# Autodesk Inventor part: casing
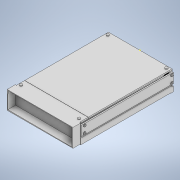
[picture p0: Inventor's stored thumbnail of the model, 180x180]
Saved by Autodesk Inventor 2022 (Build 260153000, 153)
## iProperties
Created: 2021-06
Part Number: casing
Material: Generic
Document SubType Name: Modeling
Designer: Dell
Density: 1 g/cm^3
Appearance: Default
Author: Dell
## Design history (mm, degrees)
sketch "Sketch1"
  geometry: L1 (-125, -25)-(125, -25); L2 (125, -25)-(125, 25); L3 (125, 25)-(-125, 25); L4 (-125, 25)-(-125, -25); L5 (-125, -25)-(125, 25); L6 (125, -25)-(-125, 25); 1 further point
  constraints: 12 end point, 2 midpoint, 2 parallel, 1 horizontal, 1 perpendicular
  dimensions: "d0" = 250 distance of L3.end L2.end; "d1" = 50 distance of L2.end L1.end
extrude "Extrusion1" new body sketch "Sketch1" distance "d2" = 10; taper "d3" = 0 deg
sketch "Sketch2"
  geometry: L1 (125, -25)-(125, 25) reference; L2 (-125, 25)-(-125, -25) reference; C1 r 5 at (-119.5, 17.804); C2 r 5 at (-119.5, -19.662); C3 r 5 at (119.5, -19.662); C4 r 5 at (119.5, 17.804); 1 further point
  constraints: 4 centre point
  dimensions: "d4" = 10 diameter of C1; "d5" = 10 diameter of C2; "d6" = 10 diameter of C3; "d7" = 10 diameter of C4; "d8" = 5.5 distance from line of L1 C3.centre; "d9" = 5.5 distance from line of L1 C4.centre; "d10" = 5.5 distance from line of L2 C1.centre; "d11" = 5.5 distance from line of L2 C2.centre
extrude "Extrusion2" join sketch "Sketch2" distance "d12" = 350; taper "d13" = 0 deg
sketch "Sketch3"
  geometry: C1 r 5 at (-119.5, 17.804) reference; C2 r 5.64 at (-119.5, 17.804); 1 further point
  constraints: 1 centre point, 1 coincident
extrude "Extrusion3" join sketch "Sketch3" distance "d14" = 20; taper "d15" = 0 deg
sketch "Sketch4"
  geometry: C1 r 5 at (119.5, 17.804) reference; C2 r 5.25 at (119.5, 17.804); C3 r 5.25 at (119.5, -20.116); C4 r 5.25 at (-119.54, -20.116); 1 further point
  constraints: 3 centre point, 1 coincident
  dimensions: "d16" = 10.5 diameter of C2; "d17" = 10.5 diameter of C3; "d18" = 10.5 diameter of C4
extrude "Extrusion4" join sketch "Sketch4" distance "d19" = 20; taper "d20" = 0 deg
sketch "Sketch5"
  geometry: C1 r 5 at (-99.537, 0); C2 r 5 at (-53.545, 0); C3 r 5 at (38.02, 0); C4 r 5 at (93.254, 0); 1 further point
  constraints: 4 centre point
  dimensions: "d21" = 10 diameter of C1; "d22" = 10 diameter of C2; "d23" = 10 diameter of C3; "d24" = 10 diameter of C4
extrude "Extrusion5" join sketch "Sketch5" distance "d25" = 200; taper "d26" = 0 deg
sketch "Sketch6"
  geometry: C1 r 5 at (100.739, 0); 1 further point
  constraints: 1 centre point
  dimensions: "d27" = 10 diameter of C1
extrude "Extrusion6" join sketch "Sketch6" distance "d28" = 200; taper "d29" = 0 deg
sketch "Sketch7"
  geometry: C1 r 5 at (-75.108, 0); C2 r 5 at (75.885, 0); 1 further point
  constraints: 2 centre point
  dimensions: "d30" = 10 diameter of C1; "d31" = 10 diameter of C2
extrude "Extrusion7" join sketch "Sketch7" distance "d32" = 100; taper "d33" = 0 deg
sketch "Sketch8"
  geometry: C1 r 5 at (75.885, 0) reference; C2 r 5.1 at (75.885, 0); C3 r 5 at (-75.108, 0) reference; C4 r 5.1 at (-75.108, 0); 1 further point
  constraints: 2 centre point, 2 coincident
  dimensions: "d34" = 10.2 diameter of C2; "d35" = 10.2 diameter of C4
extrude "Extrusion8" join sketch "Sketch8" distance "d36" = 150; taper "d37" = 0 deg
sketch "Sketch9"
  geometry: L1 (0, 7.931)-(-328.777, 7.931); L2 (-328.777, 7.931)-(-328.777, 45.876); L3 (-328.777, 45.876)-(0, 45.876); L4 (0, 45.876)-(0, 7.931); 1 further point
  constraints: 8 end point, 2 parallel, 1 horizontal, 1 perpendicular
extrude "Extrusion9" join sketch "Sketch9" distance "d38" = 5; taper "d39" = 0 deg
sketch "Sketch10"
  geometry: L1 (0, 45.876)-(0, 50) reference; L2 (0, 45.876)-(329.471, 45.876); L3 (329.471, 45.876)-(329.471, 4.229); L4 (329.471, 4.229)-(0, 4.229); L5 (0, 4.229)-(0, 45.876); 1 further point
  constraints: 8 end point, 2 parallel, 1 horizontal, 1 perpendicular
extrude "Extrusion10" join sketch "Sketch10" distance "d40" = 5; taper "d41" = 0 deg
sketch "Sketch11"
  geometry: L1 (249.75, 0)-(1.214, 0); L2 (1.214, 0)-(1.214, -327.338); L3 (1.214, -327.338)-(249.75, -327.338); L4 (249.75, -327.338)-(249.75, 0); 1 further point
  constraints: 8 end point, 2 parallel, 1 horizontal, 1 perpendicular
extrude "Extrusion11" join sketch "Sketch11" distance "d42" = 5; taper "d43" = 0 deg
sketch "Sketch12"
  geometry: L1 (30.654, 285.189)-(220.959, 285.189); L2 (220.959, 285.189)-(220.959, 280.351); L3 (220.959, 280.351)-(30.654, 280.351); L4 (30.654, 280.351)-(30.654, 285.189); 1 further point
  constraints: 8 end point, 2 parallel, 1 horizontal, 1 perpendicular
extrude "Extrusion12" join sketch "Sketch12" distance "d44" = 15; taper "d45" = 0 deg
sketch "Sketch13"
  geometry: 1 further point
sketch "Sketch14"
  geometry: L1 (249.5, -34.873)-(249.5, 3.072) reference; L2 (244.5, -34.873)-(244.5, 3.072) reference; L3 (249.5, -34.873)-(244.5, -34.873); L4 (244.5, -34.873)-(244.5, 3.072); L5 (244.5, 3.072)-(249.5, 3.072); L6 (249.5, 3.072)-(249.5, -34.873); L7 (244.25, 7.196)-(244.25, 12.196) reference; L8 (244.25, 7.196)-(-4.286, 7.196) reference; L9 (244.25, 12.196)-(-4.286, 12.196); L10 (-4.286, 12.196)-(-4.286, 7.196); L11 (-4.286, 7.196)-(244.25, 7.196); L12 (244.25, 7.196)-(244.25, 12.196); L13 (-5.5, -38.575)-(-10.5, -38.575) reference; L14 (-10.5, 3.072)-(-10.5, -38.575) reference; L15 (-5.5, -38.575)-(-10.5, -38.575); L16 (-10.5, -38.575)-(-10.5, 3.072); L17 (-10.5, 3.072)-(-5.5, 3.072); L18 (-5.5, 3.072)-(-5.5, -38.575); 3 further points
  constraints: 24 end point, 6 parallel, 3 horizontal, 3 perpendicular
extrude "Extrusion13" join sketch "Sketch14" distance "d46" = 32; taper "d47" = 0 deg
sketch "Sketch15"
  geometry: 1 further point
sketch "Sketch16"
  geometry: L1 (-8.634, -38.575)-(247.691, -38.575); L2 (247.691, -38.575)-(247.691, 12.196); L3 (247.691, 12.196)-(-8.634, 12.196); L4 (-8.634, 12.196)-(-8.634, -38.575); 1 further point
  constraints: 8 end point, 2 parallel, 1 horizontal, 1 perpendicular
extrude "Extrusion14" join sketch "Sketch16" distance "d48" = 2; taper "d49" = 0 deg
sketch "Sketch17"
  geometry: L1 (30.463, 210)-(20.463, 210) reference; L2 (30.463, 210)-(71.438, 137.486); L3 (71.438, 137.486)-(79.69, 142.149); L4 (79.69, 142.149)-(38.715, 214.663); L5 (38.715, 214.663)-(30.463, 210); L6 (182.656, 132.028)-(220.739, 210); L7 (220.739, 10)-(220.739, 210) reference; L8 (182.656, 132.028)-(176.036, 142.149); L9 (230.739, 210)-(220.739, 210) reference; L10 (220.739, 210)-(215.663, 218.984); L11 (215.663, 218.984)-(176.036, 142.149); 1 further point
  constraints: 16 end point, 3 perpendicular, 1 point on line
extrude "Extrusion15" join sketch "Sketch17" distance "d50" = 40; taper "d51" = 0 deg
sketch "Sketch18"
  geometry: L1 (-5, 360)-(-5, 0) reference; L2 (255, 360)-(255, 0) reference; L3 (-5, 9.92)-(255, 9.92); L4 (255, 9.92)-(255, 0); L5 (255, 0)-(-5, 0); L6 (-5, 0)-(-5, 9.92); 3 further points
  constraints: 8 end point, 2 parallel, 1 horizontal, 1 perpendicular, 1 point on line
extrude "Extrusion16" join sketch "Sketch18" distance "d52" = 20; taper "d53" = 0 deg
sketch "Sketch19"
  geometry: L1 (10, 4.229)-(360, 4.229) reference; L2 (30, 41.557)-(10, 41.557) reference; L3 (0, 7.931)-(10, 7.931) reference; C1 r 5 at (347.549, 40.186); C2 r 5 at (347.549, 9.229); C3 r 5 at (10, 41.557); C4 r 5 at (10, 7.931); 1 further point
  constraints: 4 centre point
  dimensions: "d54" = 10 diameter of C1; "d55" = 10 diameter of C2; "d56" = 5 distance from line of L1 C2.centre; "d57" = 10 diameter of C3; "d58" = 10 diameter of C4
extrude "Extrusion17" join sketch "Sketch19" distance "d59" = 2; taper "d60" = 0 deg
sketch "Sketch20"
  geometry: L1 (-0.609, 38.95)-(-0.609, 28.495); L2 (2.519, 37.944)-(-2.519, 37.944) reference; L3 (-0.609, 28.495)-(0, 28.495); L4 (0, 28.495)-(0, 38.21); L5 (0, 40.512)-(0, 29.233) reference; L6 (-0.609, 38.21)-(-0.609, 38.95); L7 (-0.609, 38.21)-(0, 38.21); 3 further points
  constraints: 10 end point, 2 point on line, 1 collinear, 1 horizontal, 1 perpendicular
extrude "Extrusion18" cut sketch "Sketch20" distance "d61" = 2; taper "d62" = 0 deg
sketch "Sketch21"
  geometry: L1 (0.419, 4.982)-(-0.435, 4.982); L2 (-0.435, 4.982)-(-0.435, -4.981); L3 (-0.435, -4.981)-(0.419, -4.981); L4 (0.419, -4.981)-(0.419, 4.982); L5 (337.549, 37.255)-(338.307, 37.255); L6 (338.307, 37.255)-(338.307, 36.579); L7 (338.307, 36.579)-(337.549, 36.579); L8 (337.549, 36.579)-(337.549, 37.255); L9 (338.307, 37.255)-(337.549, 37.255); L10 (337.549, 37.255)-(337.549, 27.255); L11 (337.549, 27.255)-(338.307, 27.255); L12 (338.307, 27.255)-(338.307, 37.255); L13 (337.549, -3.702)-(338.307, -3.702); L14 (338.307, -3.702)-(338.307, 6.24); L15 (338.307, 6.24)-(337.549, 6.24); L16 (337.549, 6.24)-(337.549, -3.702); A1 r 5 centre (0, 0) between (3.361, -3.702) and (-3.361, -3.702) reference; A2 r 5 centre (0, 0) between (-3.361, -3.702) and (3.361, -3.702) reference; A3 r 5 centre (337.549, 32.255) between (337.549, 37.255) and (337.549, 27.255) reference; A4 r 5 centre (337.549, 1.298) between (337.549, -3.702) and (338.307, 6.24) reference; 3 further points
  constraints: 32 end point, 8 parallel, 5 point on circle, 4 horizontal, 4 perpendicular, 2 point on line
extrude "Extrusion19" cut sketch "Sketch21" distance "d63" = 2; taper "d64" = 0 deg
sketch "Sketch22"
  geometry: C1 r 5 at (-347.549, 40.186); C2 r 5 at (-348.307, 14.171); C3 r 5 at (-6.62, 40.186); C4 r 5 at (-6.639, 12.912); A1 r 5 centre (-347.549, 40.186) between (-348.307, 45.129) and (-348.307, 35.244) reference; A2 r 5 centre (-347.549, 9.229) between (-348.307, 14.171) and (-348.307, 4.287) reference; 3 further points
  constraints: 4 centre point, 1 coincident
  dimensions: "d65" = 10 diameter of C1; "d66" = 10 diameter of C2; "d67" = 10 diameter of C3; "d68" = 10 diameter of C4
extrude "Extrusion20" join sketch "Sketch22" distance "d69" = 2; taper "d70" = 0 deg
sketch "Sketch23"
  geometry: L1 (-0.861, 3.238)-(0.719, 3.238); L2 (0.719, 3.238)-(0.719, -5.192); L3 (0.719, -5.192)-(-0.861, -5.192); L4 (-0.861, -5.192)-(-0.861, 3.238); L5 (-0.861, -22.345)-(0.719, -22.345); L6 (0.719, -22.345)-(0.719, -29.392); L7 (0.719, -29.392)-(-0.861, -29.392); L8 (-0.861, -29.392)-(-0.861, -22.345); L9 (-342.471, 3.238)-(-340.304, 3.238); L10 (-340.304, 3.238)-(-340.304, -5.192); L11 (-340.304, -5.192)-(-342.471, -5.192); L12 (-342.471, -5.192)-(-342.471, 3.238); L13 (-341.687, -21.015)-(-340.929, -21.015); L14 (-340.929, -21.015)-(-340.929, -30.957); L15 (-340.929, -30.957)-(-341.687, -30.957); L16 (-341.687, -30.957)-(-341.687, -21.015); A1 r 5 centre (-0.019, -27.274) between (0.416, -32.255) and (-0.455, -32.255) reference; A2 r 5 centre (-3.38, -32.255) between (-2.945, -37.236) and (-2.945, -27.274) reference; A3 r 5 centre (-340.929, -30.957) between (-341.687, -26.015) and (-341.687, -35.899) reference; 1 further point
  constraints: 32 end point, 8 parallel, 4 horizontal, 4 perpendicular, 4 point on line, 2 point on circle, 1 vertical alignment, 1 other
extrude "Extrusion21" cut sketch "Sketch23" distance "d71" = 2; taper "d72" = 0 deg
sketch "Sketch24"
  geometry: L1 (10.5, -30)-(10.5, -360) reference; L2 (7.386, -10)-(242.574, -10) reference; C1 r 5 at (237.545, -351.159); C2 r 5 at (10.5, -351.159); C3 r 5 at (10.5, -12.076); C4 r 5 at (237.545, -10); 1 further point
  constraints: 4 centre point, 2 point on line
  dimensions: "d73" = 10 diameter of C1; "d74" = 10 diameter of C2; "d75" = 10 diameter of C3; "d76" = 10 diameter of C4
extrude "Extrusion22" join sketch "Sketch24" distance "d77" = 3; taper "d78" = 0 deg
sketch "Sketch25"
  geometry: 1 further point
sketch "Sketch26"
  geometry: L1 (-9.161, 0)-(-13.51, 0) reference; L2 (-13.51, 0)-(-9.161, 0); L3 (-10.375, -350)-(-10.375, 0) reference; L4 (-9.161, 0)-(-10.375, -350); L5 (-15.375, -349.581)-(-15.375, -346.639) reference; L6 (-10.375, -350)-(-15.375, -346.639); L7 (-15.375, -11.693)-(-15.375, -7.451) reference; L8 (-15.375, -346.639)-(-13.51, 0); L9 (242.815, 0)-(244.625, 0) reference; L10 (244.625, 0)-(244.625, -352.925) reference; L11 (244.625, 0)-(244.625, -352.925); L12 (244.625, -352.925)-(239.375, -352.925); L13 (239.375, 0)-(239.375, -32) reference; L14 (239.375, -352.925)-(239.375, 0); L15 (239.375, 0)-(244.625, 0); 3 further points
  constraints: 16 end point, 2 collinear, 2 perpendicular, 1 horizontal
extrude "Extrusion23" join sketch "Sketch26" distance "d79" = 23; taper "d80" = 0 deg
sketch "Sketch27"
  geometry: L1 (-13.51, 0)-(-13.51, 2) reference; L2 (244.625, 0)-(239.375, 0) reference; L3 (-13.51, 2)-(244.625, 2); L4 (244.625, 2)-(244.625, 0); L5 (244.625, 0)-(-13.51, 0); L6 (-13.51, 0)-(-13.51, 2); 3 further points
  constraints: 8 end point, 2 parallel, 1 horizontal, 1 perpendicular
extrude "Extrusion24" join sketch "Sketch27" distance "d81" = 23; taper "d82" = 0 deg
sketch "Sketch28"
  geometry: L1 (-10.375, 0)-(-9.751, 0) reference; L2 (239.625, -360)-(239.625, -350) reference; L3 (-10.375, 0)-(239.625, 0); L4 (239.625, 0)-(239.625, -355); L5 (239.625, -355)-(-10.375, -355); L6 (-10.375, -355)-(-10.375, 0); 3 further points
  constraints: 8 end point, 2 parallel, 1 horizontal, 1 midpoint, 1 perpendicular
extrude "Extrusion25" join sketch "Sketch28" distance "d83" = 2; taper "d84" = 0 deg
sketch "Sketch29"
  geometry: L1 (239.625, 0)-(-10.375, 0) reference; L2 (239.625, -350.08)-(239.625, -355) reference; L3 (-10.375, 0)-(239.625, 0); L4 (239.625, 0)-(239.625, -355); L5 (239.625, -355)-(-10.375, -355); L6 (-10.375, -355)-(-10.375, 0); 3 further points
  constraints: 8 end point, 2 parallel, 1 horizontal, 1 perpendicular
extrude "Extrusion26" cut sketch "Sketch29" distance "d85" = 5; taper "d86" = 0 deg
sketch "Sketch30"
  geometry: 1 further point
sketch "Sketch31"
  geometry: 1 further point
sketch "Sketch32"
  geometry: C1 r 5.1 at (0, 0); C2 r 5.1 at (200.277, 0); A1 r 5 centre (200.277, 0) between (195.277, 0) and (205.277, 0) reference; 3 further points
  constraints: 2 centre point, 2 coincident, 1 horizontal alignment
  dimensions: "d87" = 10.2 diameter of C1; "d88" = 10.2 diameter of C2
extrude "Extrusion27" cut sketch "Sketch32" distance "d89" = 200; taper "d90" = 0 deg
sketch "Sketch33"
  geometry: 1 further point
sketch "Sketch34"
  geometry: 1 further point
sketch "Sketch35"
  geometry: C1 r 5.1 at (75.885, 0); C2 r 5.1 at (-75.108, 0) reference; C3 r 5.1 at (-75.108, 0); A1 r 5 centre (75.885, 0) between (71.318, -2.036) and (71.318, 2.036) reference; 1 further point
  constraints: 2 centre point, 2 coincident
  dimensions: "d91" = 10.2 diameter of C1; "d92" = 10.2 diameter of C3
extrude "Extrusion28" cut sketch "Sketch35" distance "d93" = 150; taper "d94" = 0 deg
sketch "Sketch36"
  geometry: L1 (190.818, -20.075)-(190.818, -15.534) reference; C1 r 10 at (190.818, -15.534); C2 r 10 at (59.499, -15.534); 1 further point
  constraints: 2 centre point
  dimensions: "d95" = 20 diameter of C1; "d97" = 20 diameter of C2
sketch "Sketch37"
  geometry: 1 further point
sketch "Sketch38"
  geometry: L1 (-8.634, 12.196)-(-8.634, 3.072) reference; L2 (-8.634, 12.196)-(248.986, 12.196); L3 (248.986, 12.196)-(248.986, -58.575); L4 (248.986, -58.575)-(-8.634, -58.575); L5 (-8.634, -58.575)-(-8.634, 12.196); L6 (-0.301, 9.828)-(244.25, 9.828); L7 (244.25, 7.196)-(-4.286, 7.196) reference; L8 (244.25, 9.828)-(244.25, -56.252); L9 (244.25, -56.252)-(-5.5, -54.724); L10 (-5.5, -54.724)-(-5.105, 9.828); L11 (-5.105, 9.828)-(-0.301, 9.828); C1 r 10 at (43.57, -17.804); 2 further points
  constraints: 18 end point, 3 parallel, 2 perpendicular, 1 centre point, 1 collinear, 1 horizontal, 1 point on line
  dimensions: "d96" = 20 diameter of C1
extrude "Extrusion29" join sketch "Sketch36" distance "d98" = 15; taper "d99" = 0 deg
sketch "Sketch39"
  geometry: 1 further point
sketch "Sketch40"
  geometry: L1 (38.587, 105.488)-(208.523, 105.488); L2 (38.587, 105.488)-(38.587, 97.395); L3 (38.587, 97.395)-(208.523, 97.395); L4 (208.523, 97.395)-(208.523, 105.488); 1 further point
  constraints: 8 end point, 2 perpendicular, 1 horizontal, 1 vertical
extrude "Extrusion30" join sketch "Sketch40" distance "d100" = 40; taper "d101" = 0 deg
sketch "Sketch41"
  geometry: L1 (22.478, -5)-(150.349, -5); L2 (150.349, -5)-(150.349, -35); L3 (150.349, -35)-(22.478, -35); L4 (22.478, -35)-(22.478, -5); L5 (25.478, -8)-(144.735, -8); L6 (0, 0)-(169.936, 0) reference; L7 (25.478, -32.733)-(25.478, -8); L8 (169.936, -40)-(0, -40) reference; L9 (25.478, -32.733)-(144.735, -31.501); L10 (144.735, -31.501)-(149.152, -31.455); L11 (149.152, -31.455)-(148.909, -7.957); L12 (148.909, -7.957)-(144.735, -8); 1 further point
  constraints: 20 end point, 3 perpendicular, 2 horizontal, 2 parallel, 1 point on line, 1 vertical
  dimensions: "d102" = 5 distance between parallel lines of L1 L6; "d103" = 3 distance between parallel lines of L5 L1; "d104" = 3 distance between parallel lines of L7 L4; "d105" = 5 distance between parallel lines of L8 L3
extrude "Extrusion31" join sketch "Sketch41" distance "d106" = 17; taper "d107" = 0 deg
extrude "Extrusion32" join sketch "Sketch38" distance "d108" = 30; taper "d109" = 0 deg
body "Solid1"
